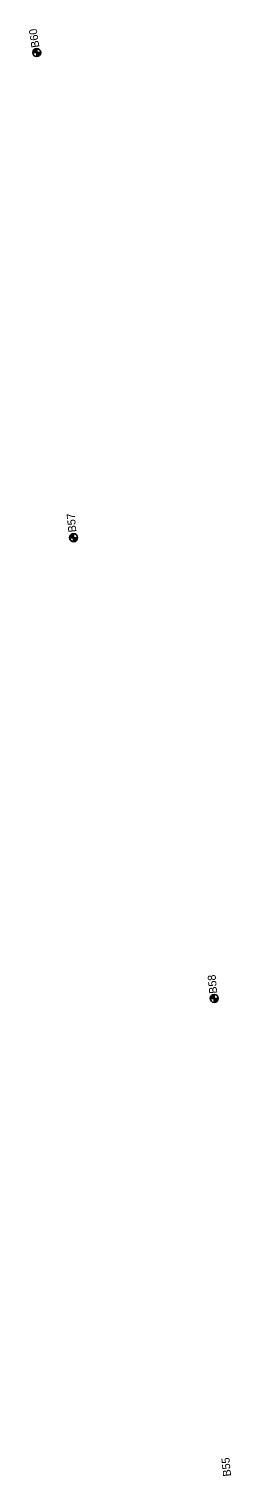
# Model space of a CAD drawing. Extents: x 331323 to 388339, y 121519 to 205315.
# Drawn here: x 359888 to 360141, y 160534 to 162343 of the extents above; entities that cross this region are included whole.
import ezdxf

# ---------------------------------------------------------------- set-up
doc = ezdxf.new("R2010")
doc.units = 0
for name, color, linetype in [('E_SOIL_BORE1 [KAPUR_CADDS_LEVELS]', 7, 'Continuous'), ('E_SOIL_BORE2 [KAPUR_CADDS_LEVELS]', 7, 'Continuous'), ('P_MARK', 7, 'Continuous')]:
    doc.layers.add(name, color=color, linetype=linetype)

msp = doc.modelspace()

# ---------------------------------------------------------------- linework, layer by layer
at = {"layer": 'P_MARK'}
for p, q in [((359892.4, 162313.3), (359902.4, 162313.3)), ((359897.4, 162318.3), (359897.4, 162308.3)), ((359943.5, 161711.9), (359943.5, 161701.9)), ((359938.5, 161706.9), (359948.5, 161706.9)), ((360114.5, 161131), (360124.5, 161131)), ((360119.5, 161136), (360119.5, 161126))]:
    msp.add_line(p, q, dxfattribs=at)
for centre in [(359897.4, 162313.3), (359943.5, 161706.9), (360119.5, 161131)]:
    msp.add_circle(centre, 5, dxfattribs=at)
for centre, radius, start, end in [((359897.4, 162313.3), 4.5, 89.9869, 179.9869), ((359897.4, 162313.3), 4, 89.9869, 179.9869), ((359897.4, 162313.3), 3.5, 89.9869, 179.9869), ((359897.4, 162313.3), 3, 89.9869, 179.9869), ((359897.4, 162313.3), 2.5, 89.9869, 179.9869), ((359897.4, 162313.3), 2, 89.9869, 179.9869), ((359897.4, 162313.3), 1.5, 89.9869, 179.9869), ((359897.4, 162313.3), 1, 89.9869, 179.9869), ((359897.4, 162313.3), 0.5, 89.9869, 179.9869), ((359897.4, 162313.3), 4.5, 269.9869, 359.9869), ((359897.4, 162313.3), 4, 269.9869, 359.9869), ((359897.4, 162313.3), 3.5, 269.9869, 359.9869), ((359897.4, 162313.3), 3, 269.9869, 359.9869), ((359897.4, 162313.3), 2.5, 269.9869, 359.9869), ((359897.4, 162313.3), 2, 269.9869, 359.9869), ((359897.4, 162313.3), 1.5, 269.9869, 359.9869), ((359897.4, 162313.3), 1, 269.9869, 359.9869), ((359897.4, 162313.3), 0.5, 269.9869, 359.9869), ((359943.5, 161706.9), 4.5, 89.9869, 179.9869), ((359943.5, 161706.9), 4, 89.9869, 179.9869), ((359943.5, 161706.9), 3.5, 89.9869, 179.9869), ((359943.5, 161706.9), 3, 89.9869, 179.9869), ((359943.5, 161706.9), 2.5, 89.9869, 179.9869), ((359943.5, 161706.9), 2, 89.9869, 179.9869), ((359943.5, 161706.9), 1.5, 89.9869, 179.9869), ((359943.5, 161706.9), 1, 89.9869, 179.9869), ((359943.5, 161706.9), 0.5, 89.9869, 179.9869), ((359943.5, 161706.9), 4.5, 269.9869, 359.9869), ((359943.5, 161706.9), 4, 269.9869, 359.9869), ((359943.5, 161706.9), 3.5, 269.9869, 359.9869), ((359943.5, 161706.9), 3, 269.9869, 359.9869), ((359943.5, 161706.9), 2.5, 269.9869, 359.9869), ((359943.5, 161706.9), 2, 269.9869, 359.9869), ((359943.5, 161706.9), 1.5, 269.9869, 359.9869), ((359943.5, 161706.9), 1, 269.9869, 359.9869), ((359943.5, 161706.9), 0.5, 269.9869, 359.9869), ((360119.5, 161131), 4.5, 89.9869, 179.9869), ((360119.5, 161131), 4, 89.9869, 179.9869), ((360119.5, 161131), 3.5, 89.9869, 179.9869), ((360119.5, 161131), 3, 89.9869, 179.9869), ((360119.5, 161131), 2.5, 89.9869, 179.9869), ((360119.5, 161131), 2, 89.9869, 179.9869), ((360119.5, 161131), 1.5, 89.9869, 179.9869), ((360119.5, 161131), 1, 89.9869, 179.9869), ((360119.5, 161131), 0.5, 89.9869, 179.9869), ((360119.5, 161131), 4.5, 269.9869, 359.9869), ((360119.5, 161131), 4, 269.9869, 359.9869), ((360119.5, 161131), 3.5, 269.9869, 359.9869), ((360119.5, 161131), 3, 269.9869, 359.9869), ((360119.5, 161131), 2.5, 269.9869, 359.9869), ((360119.5, 161131), 2, 269.9869, 359.9869), ((360119.5, 161131), 1.5, 269.9869, 359.9869), ((360119.5, 161131), 1, 269.9869, 359.9869), ((360119.5, 161131), 0.5, 269.9869, 359.9869)]:
    msp.add_arc(centre, radius, start, end, dxfattribs=at)

# ---------------------------------------------------------------- texts
at = {"layer": 'E_SOIL_BORE1 [KAPUR_CADDS_LEVELS]'}
for s, rotation, p in [('B60', 98.5151, (359900.8, 162320.1)), ('B57', 95.5802, (359947, 161714.1))]:
    msp.add_text(s, height=10, rotation=rotation, dxfattribs=at).set_placement(p)
at = {"layer": 'E_SOIL_BORE2 [KAPUR_CADDS_LEVELS]'}
for s, p in [('B58', (360123.4, 161137.4)), ('B55', (360140.7, 160533.9))]:
    msp.add_text(s, height=10, rotation=95.5802, dxfattribs=at).set_placement(p)

doc.saveas('drawing.dxf')
